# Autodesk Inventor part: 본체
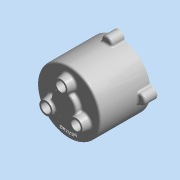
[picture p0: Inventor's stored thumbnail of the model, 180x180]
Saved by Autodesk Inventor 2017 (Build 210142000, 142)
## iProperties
Created: 2021-07
Part Number: 본체
Document SubType Name: 모델링
Designer: mdu
Material: 알루미늄 6061
Density: 2.71 g/cm^3
Mass: 473.477 g
Surface Area: 688.944 cm^2
Volume: 174.715 cm^3
Appearance: 알루미늄 - 평지
변환 표준: STEP AP214IS
파일 이름: C:\Users\SeoGD\Desktop\?쒗뿕\紐몄껜.stp
전처리기: Build: 253, Release: 2010 SP1 - Date: Wed 07/29/2009
전송 단위: 밀리미터
불확실성: 0.01
Author: mdu
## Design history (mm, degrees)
sketch "스케치2"
  geometry: C1 r 50 at (0, 0); 1 further point
  constraints: 1 centre point, 1 coincident
  dimensions: "d9" = 100 diameter of C1
extrude "돌출2" new body sketch "스케치2" distance "d10" = 80; taper "d11" = 0 deg
feature "쉘1" dims "d12" = 5
sketch "스케치3" dims "d13" = 55
  geometry: C1 r 7.5 at (0, 27.5); C2 r 12.5 at (0, 27.5); 2 further points
  constraints: 2 centre point, 2 coincident, 2 vertical alignment, 2 other
  dimensions: "d14" = 15 diameter of C1; "d15" = 25 diameter of C2
extrude "돌출3" join sketch "스케치3" distance "d16" = 12; taper "d17" = -10 deg
sketch "스케치4"
  geometry: L1 (0, 0)-(0, 88); L2 (0, 70)-(14, 70); L3 (-45, 75)-(45, 75) reference; L4 (-50, 80)-(50, 80) reference; L5 (14, 70)-(14, 75); L6 (20, 80)-(20, 88); L7 (20, 88)-(0, 88); L8 (20, 80)-(14, 75)
  constraints: 12 end point, 3 point on line, 2 perpendicular, 1 vertical
  dimensions: "d34" = 40 diameter of L6 L1; "d35" = 90 deg angle of L5 L3; "d36" = 5 distance between parallel lines of L2 L3; "d37" = 8 distance between parallel lines of L7 L4; "d51" = 28 diameter of L5.end L1
revolve "회전1" sketch "스케치4" stored, may be unused: angle "d38" = 90 deg
hole "구멍3" diameter "d41" = 15; stored, may be unused: countersink angle "d45" = 90 deg, drill point angle "d47" = 0 deg; dims "d39" = 10, "d40" = 10, "d42" = 6, "d43" = 22, "d44" = 13, "d46" = 15
chamfer "모따기2" distance "d48" = 1; stored, may be unused: second distance "d49" = 2, angle "d50" = 45 deg
fillet "모깎기4" dims "d78" = 3
hole "구멍2" diameter "d20" = 15; stored, may be unused: countersink angle "d24" = 90 deg, drill point angle "d26" = 118 deg; dims "d21" = 6, "d22" = 25, "d23" = 1, "d25" = 15, "d76" = 10, "d77" = 10
chamfer "모따기1" distance "d27" = 1; stored, may be unused: second distance "d28" = 2, angle "d29" = 45 deg
sketch "스케치9"
  geometry: C1 r 12.5 at (0, 0) reference; C2 r 12.5 at (-23.816, -41.25) reference; C3 r 12.5 at (23.816, -41.25) reference; 1 further point
extrude "돌출5" cut sketch "스케치9" stored distance "d79" = 10; taper "d80" = 0 deg
fillet "모깎기1" dims "d52" = 3
fillet "모깎기2" dims "d53" = 3, "d72" = 0.2
sketch "스케치5"
  geometry: A1 r 50 centre (0, 0) between (50, 0) and (-8.074, 49.344) reference; A2 r 8.5 centre (0, 52) between (8.074, 49.344) and (-8.074, 49.344); 1 further point
  constraints: 5 point on circle, 1 centre point, 1 horizontal alignment
  dimensions: "d54" = 90 deg dimension on point (0, 0) A2.centre A1.start; "d55" = 52 distance of A2.centre point (0, 0); "d56" = 17 diameter of A2
extrude "돌출4" join sketch "스케치5" distance "d57" = 20; taper "d58" = 0 deg
fillet "모깎기3" dims "d59" = 3
hole "구멍4" diameter "d62" = 4.134; stored, may be unused: countersink angle "d66" = 90 deg, drill point angle "d68" = 118 deg; dims "d60" = 10, "d61" = 10, "d63" = 12, "d64" = 22, "d65" = 13, "d67" = 15
sketch "스케치6"
  geometry: C1 r 47 at (0, 0) reference; C2 r 42.5 at (0, 0); 1 further point
  constraints: 1 centre point, 1 coincident, 1 other
  dimensions: "d73" = 85 diameter of C2
feature "엠보싱1" sketch "스케치6" dims "d34" = 40, "d35" = 90 deg, "d36" = 5, "d37" = 8, "d51" = 28, "d74" = 1, "d75" = 0
node "솔리드1"
node "솔리드 본체"
node "곡면 본체"
pattern_circular "원형 패턴1" dims angle "d31" = 360 deg
pattern_circular "원형 패턴2" dims angle "d70" = 360 deg
node "솔리드2"
